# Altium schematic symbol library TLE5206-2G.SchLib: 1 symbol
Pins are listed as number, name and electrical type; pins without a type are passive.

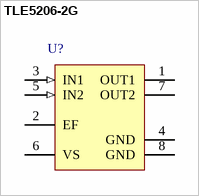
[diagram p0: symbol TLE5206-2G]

## TLE5206-2G
designator U?
5 A H-Bridge for DC-Motor Applications, 6 to 40 V, 220 mOhm RDS(on), PG-TO263-7-1, Reel, Green; Manufacturer: Infineon; PartNumber: TLE5206-2G; Current Limit (min.): 6 A; Green: TRUE; Operating Range: 6 to 40 V; Quiescent Current (max.): 10 mA; RthJC (max): 3 K/W
footprint INF-PG-TO263-7-1_N (DPAK, 8-Leads, Body 10x9.25mm, Pitch 1.27mm, IPC Medium Density)
footprint INF-PG-TO263-7-1_L (DPAK, 8-Leads, Body 10x9.25mm, Pitch 1.27mm, IPC High Density)
footprint INF-PG-TO263-7-1_M (DPAK, 8-Leads, Body 10x9.25mm, Pitch 1.27mm, IPC Low Density)
pins: 1 OUT1 (power) "Output of Channel 1; Short-circuit protected; integrated freewheeling diodes for inductive loads", 2 EF (oc) "Error Flag; TTL/CMOS compatible output for error detection; (open drain)", 3 IN1 (in) "Control Input 1; TTL/CMOS compatible", 4 GND (power) "Ground; internally connected to tab", 5 IN2 (in) "Control Input 2; TTL/CMOS compatible", 6 VS (power) "Supply Voltage; block to GND", 7 OUT2 (power) "Output of Channel 2; Short-circuit protected;  integrated freewheeling diodes for inductive loads.", 8 GND (power) "Ground; internally connected to tab"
